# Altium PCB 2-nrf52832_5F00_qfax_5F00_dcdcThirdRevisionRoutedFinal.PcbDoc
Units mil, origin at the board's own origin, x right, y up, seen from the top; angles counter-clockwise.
Board outline 1524 x 818 mil, 2 copper layers (Top Layer, Bottom Layer), stack 62.8 mil thick; 31 components, 49 nets, 125 pads, 86 vias.
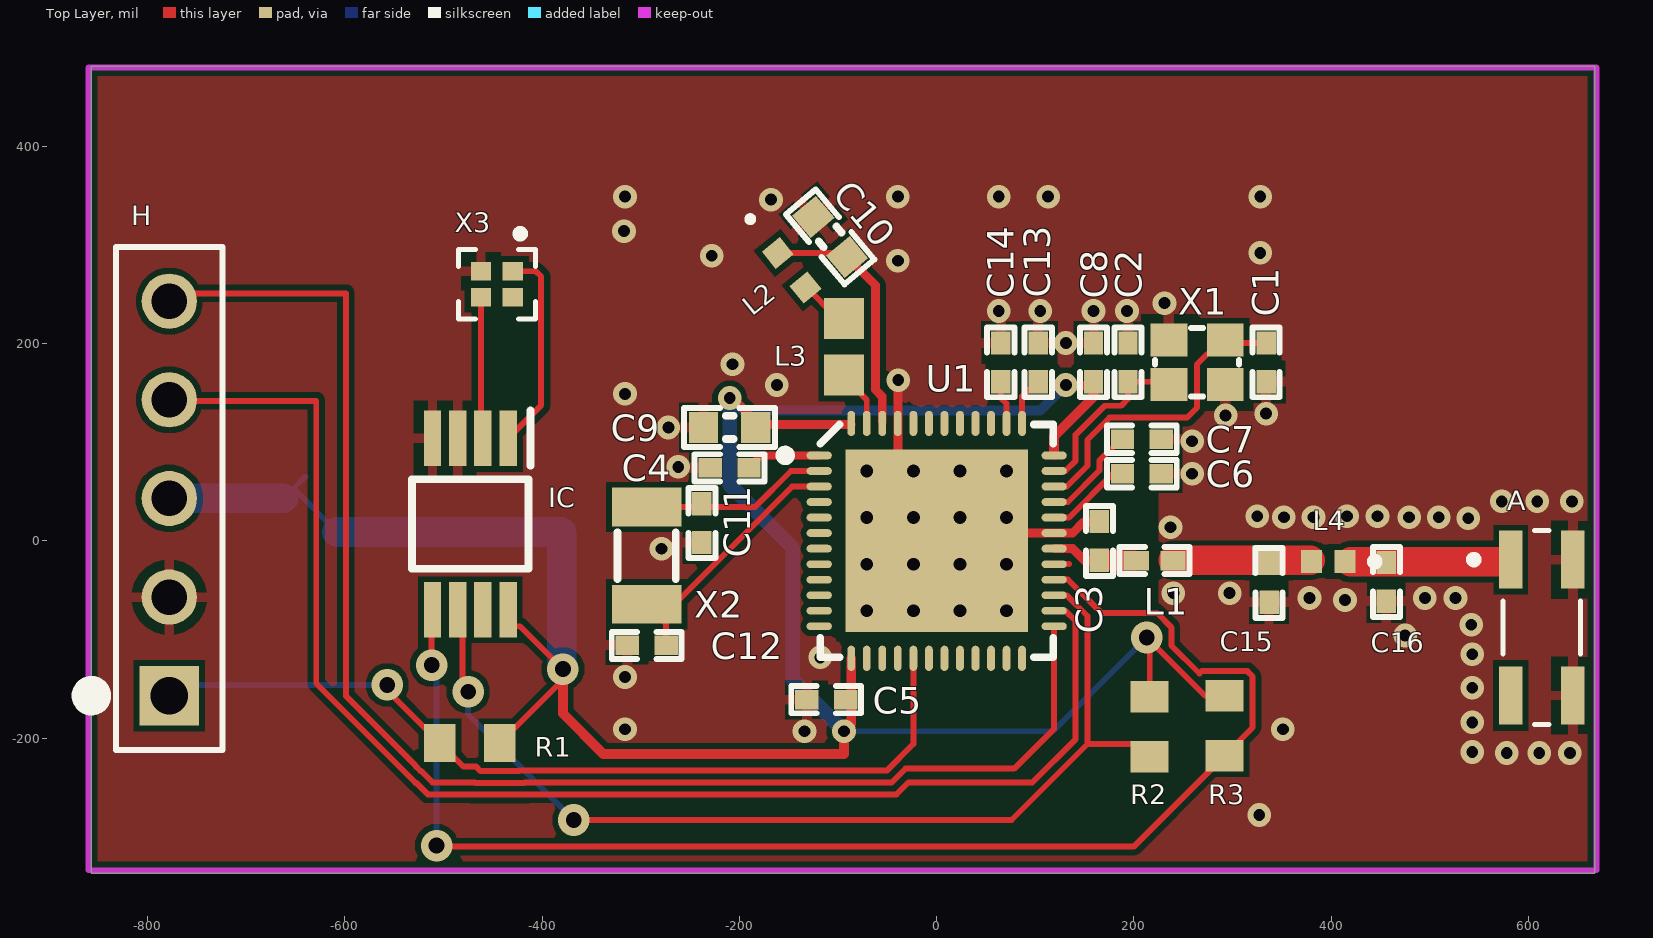
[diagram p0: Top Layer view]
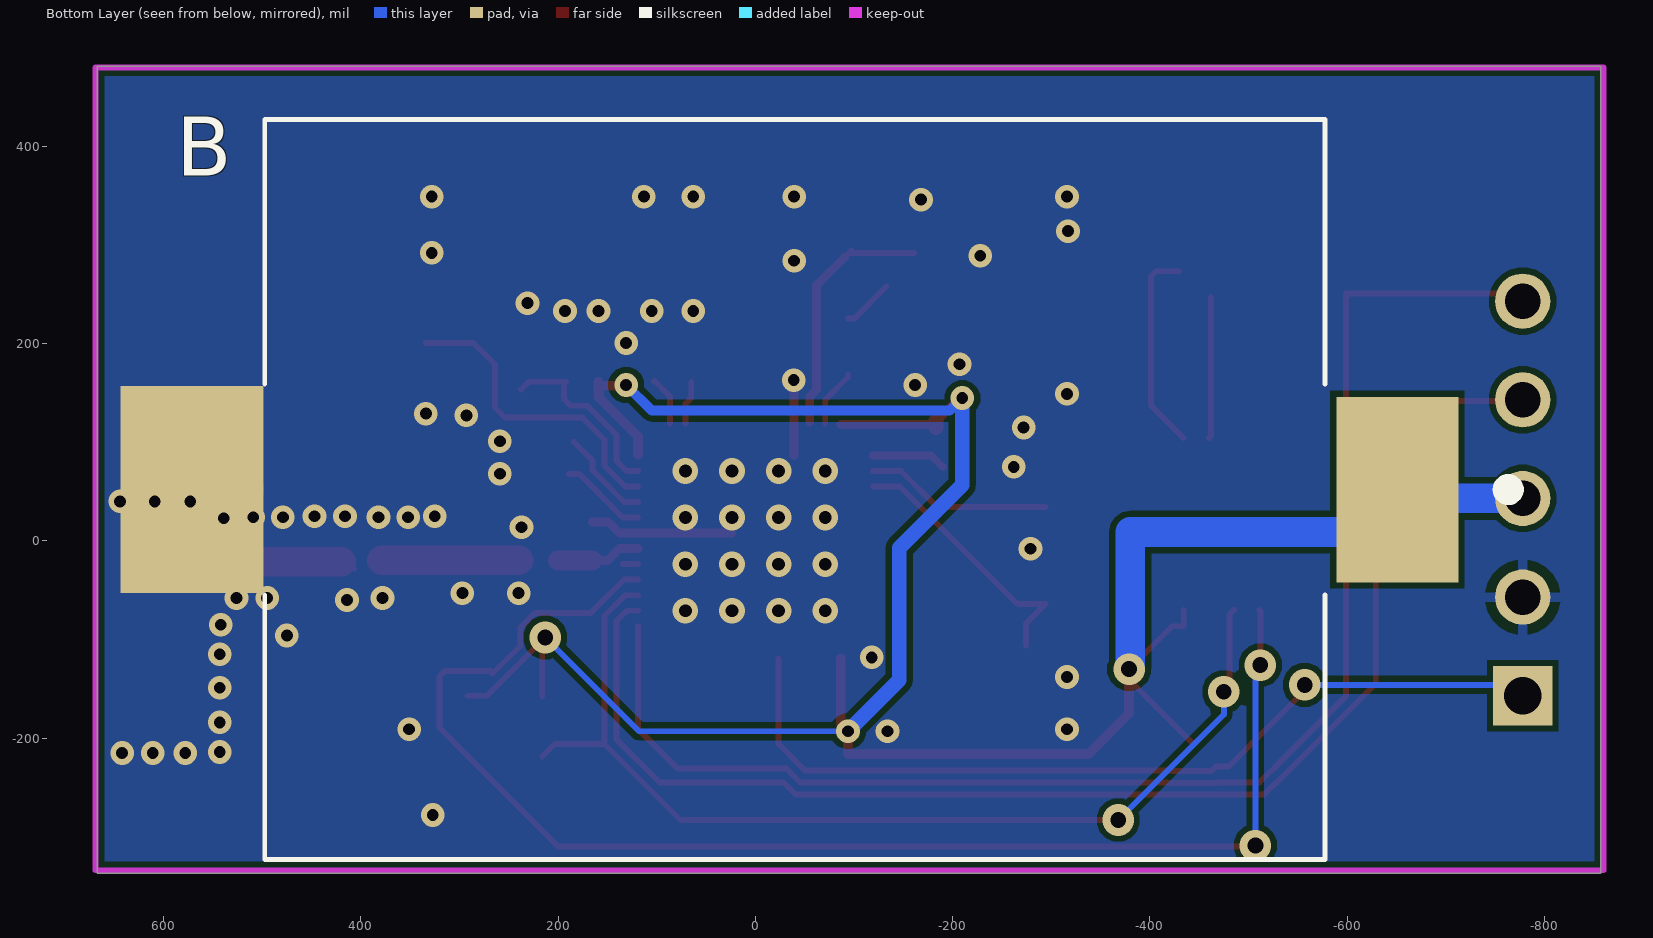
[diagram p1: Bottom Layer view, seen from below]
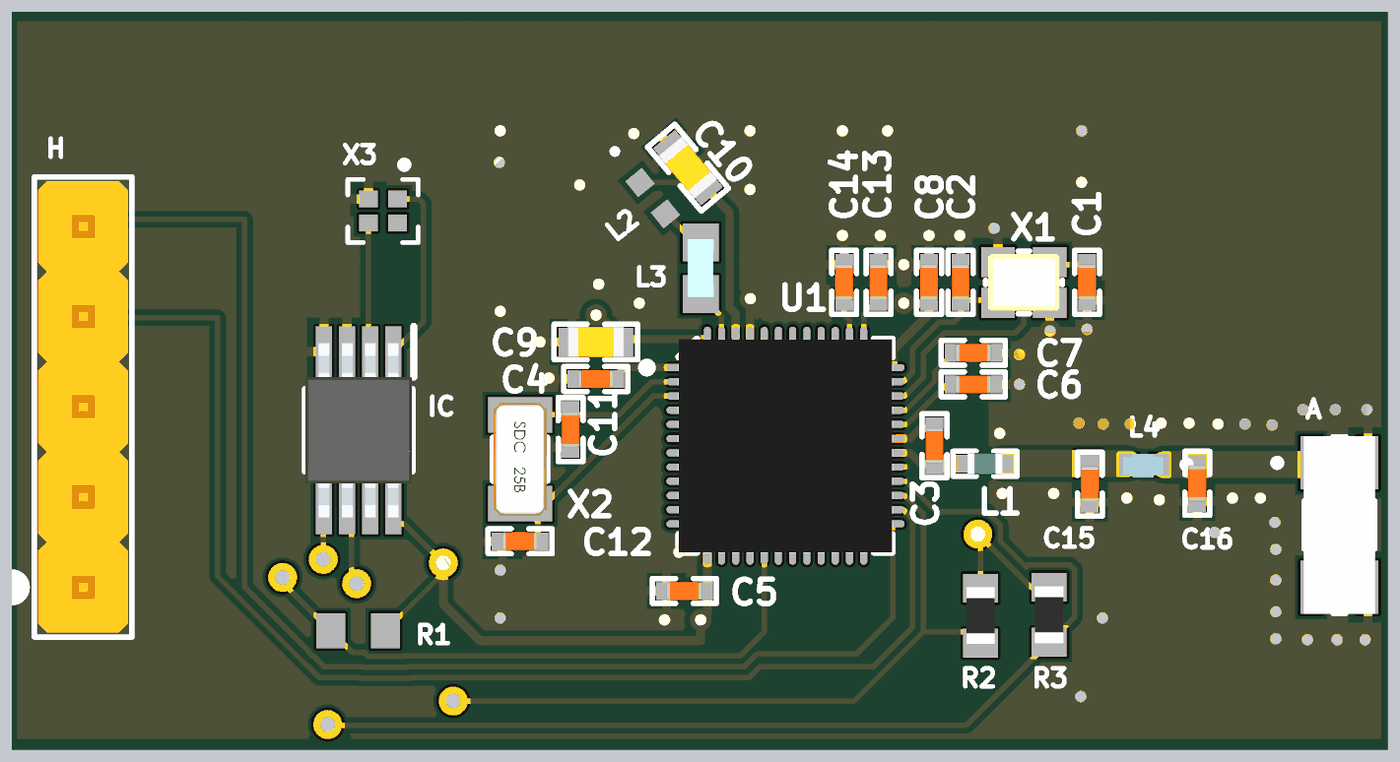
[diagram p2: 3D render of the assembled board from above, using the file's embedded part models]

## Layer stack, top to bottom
Top Solder: solder mask 0.4, Solder Resist, Dk 3.5
Top Layer: signal copper 1.4
Dielectric1: core 60, FR-4, Dk 4.8
Bottom Layer: signal copper 1.4
Bottom Solder: solder mask 0.4, Solder Resist, Dk 3.5

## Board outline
-857,-337 -857,481 667,481 667,-337

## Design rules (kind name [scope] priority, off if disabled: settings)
Clearance Polygon_ANT [(InNamedPolygon('Top_Layer-GND')) or (InNamedPolygon('Bottom_Layer-GND')) vs InNet('RF')] p1: gap=5 ignorepadtopadclearanceinfootprint=FALSE except(0: Arc-Hole Track-Hole SMDPad-Hole THPad-Hole Via-Hole Fill-Hole Poly-Hole Region-Hole Text-Hole)
Clearance Polygon [(InNamedPolygon('Top_Layer-GND')) or (InNamedPolygon('Bottom_Layer-GND'))] p2: gap=10 ignorepadtopadclearanceinfootprint=FALSE except(0: Arc-Hole Track-Hole SMDPad-Hole THPad-Hole Via-Hole Fill-Hole Poly-Hole Region-Hole Text-Hole)
Clearance [All] p3: gap=6 ignorepadtopadclearanceinfootprint=FALSE except(0: Arc-Hole Track-Hole SMDPad-Hole THPad-Hole Via-Hole Fill-Hole Poly-Hole Region-Hole Text-Hole)
ComponentClearance [All] p1 off: gap=10 collisioncheckmode=3 verticalgap=10 showdistances=FALSE
FabricationTestPointUsage TestPointUsage [All] p1: valid=0 allowmultiple=FALSE
FabricationTestpoint Testpoint [All] p1: side=3 testpointundercomponent=TRUE minsize=40 maxsize=100 preferedsize=60 minholesize=0 maxholesize=40 preferedholesize=32 testpointgrid=1 allowsidetop=TRUE allowsidebottom=TRUE usegrid=TRUE gridtolerance=0.01
Height [All] p1 off: minheight=0 maxheight=1000 prefheight=500
HoleSize [All] p1: absolutevalues=TRUE maxlimit=160 minlimit=12 maxpercent=80.000 minpercent=20.000
MinimumAnnularRing [All] p1 off: minimumring=6
PolygonConnect PolygonConnect_1 [isVia and innet(gnd)] p1: connectstyle=Direct reliefconductorwidth=10 reliefentries=4 polygonreliefangle="90 Angle" airgapwidth=10
PolygonConnect [All] p2: connectstyle=Relief reliefconductorwidth=10 reliefentries=4 polygonreliefangle="90 Angle" airgapwidth=10
RoutingVias [All] p1: holewidth=16 width=32 viastyle="Through Hole" minholewidth=10 minwidth=10 maxholewidth=28 maxwidth=50
SilkToSolderMaskClearance SilkscreenOverComponentPads [IsPad] p1: minsilkscreentomaskgap=10 clearancetoexposedcopper=TRUE
SolderMaskExpansion [All] p1: expansion=3 istentingtop=FALSE
Width [All] p1: maxlimit=110 minlimit=6 preferedwidth=6 minimp=50.000000 maximp=50.000000 favimp=50.000000
24 further rules are at their usual default settings.

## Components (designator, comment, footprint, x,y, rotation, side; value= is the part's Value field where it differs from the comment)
A "2.4 GHz Antenna" XDCR_2450AT42E010BE 613.5,-87.9 r90 top
B "Cr2032 Battery Holder" TE_796136-1 -39.98,52 r0 bottom
C1 "12pF" CAPC1005X04L 333.99,181.01 r270 top
C2 "12pF" CAPC1005X04L 193.99,181.01 r90 top
C3 "0.8pF" CAPC1005X04L 165,0 r270 top
C4 "100nF" CAPC1005X04L -210,74 r180 top
C5 "100nF" CAPC1005X04L -112,-161 r180 top
C6 "N.C." CAPC1005X04L 208,68 r180 top
C7 "100pF" CAPC1005X04L 208,103 r0 top
C8 "100nF" CAPC1005X04L 158.99,181.01 r90 top
C9 "4.7µF" CAPC1608X06L -210,115 r180 top
C10 "1.0µF" CAPC1608X06L -107.97,308.2 r310 top
C11 "12pF" CAPC1005X04L -238,18 r270 top
C12 "12pF" CAPC1005X04L -294,-106 r180 top
C13 "12pF" CAPC1005X04L 102.99,181.01 r90 top
C14 "12pF" CAPC1005X04L 64.99,181.01 r90 top
C15 "12pF" CAPC1005X04L 337,-42.69 r90 top
C16 "12pF" CAPC1005X04L 456,-41.69 r90 top
H "5 Pin Header" 22-28-4052 -778,-157 r270 top
IC "DS1339U-33+" SOP65P490X110-8N -472.8,17.09 r270 top
L1 "3.9nH" INDC1005X04L 221,-20 r0 top
L2 "0402 15nH L" IND_1005_TDK -147.07,274.37 r309 top
L3 "0603 10uH L" INDC1608X100N -94,196.66 r90 top
L4 "1.5nH Inductor" INDC1005X55N 397.01,-21 r0 top
R1 "4.7K R" RESC1508X55N -473.35,-205 r0 top
R2 "4.7K R" RESC1508X55N 216,-188.35 r90 top
R3 "4.7K R" RESC1508X55N 292,-187.35 r90 top
U1 "nRF52832-QFAA" QFN40P600X600X90-48N 0,0 r0 top locked
X1 "32MHz" BT-XTAL_2016 263.99,181.01 r180 top
X2 "32.768kHz" XTAL_3215 -294,-15 r270 top
X3 "32.7k oscillator 6pF" XTAL_ECS-.327-6-1210B-N-TR -445.86,260.19 r270 top

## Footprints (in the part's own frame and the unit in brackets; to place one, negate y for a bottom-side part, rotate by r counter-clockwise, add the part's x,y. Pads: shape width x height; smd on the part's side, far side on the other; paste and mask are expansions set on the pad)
22-28-4052 [mil]
  rect 60x60 hole 38 mask+0: 1(0,0)
  round 56 hole 36 mask+0: 2(-100,0) 3(-200,0) 4(-300,0) 5(-400,0)
  silkscreen extent -455,-89 55,54, body extent -450,-50 50,50, height 363
BT-XTAL_2016 [mm]
  rect 0.95x0.85 smd: 1(-0.725,-0.575) 2(0.725,-0.575) 3(0.725,0.575) 4(-0.725,0.575)
  silkscreen extent -1.08,-0.88 1.08,0.88, body extent -1,-0.8 1,0.8, height 0.51
CAPC1005X04L [mm]
  rect 0.6x0.5 smd: 1(-0.5,0) 2(0.5,0)
  silkscreen extent -0.9,-0.35 0.9,0.35, body extent -0.51,-0.25 0.51,0.25, height 0.5
CAPC1608X06L [mm]
  rect 0.75x0.8 smd: 1(-0.675,0) 2(0.675,0)
  silkscreen extent -1.17,-0.5 1.17,0.5, body extent -0.8,-0.43 0.8,0.43, height 0.8
IND_1005_TDK [mm]
  rect 0.576x0.6 smd paste+0 mask+0: 1(-0.568,0) 2(0.568,0)
  silkscreen extent -1.77,-0.08 -1.62,0.08, body extent 0,0 0.25,0.25, height 0.25
INDC1005X04L [mm]
  rect 0.65x0.5 smd: 1(-0.475,0) 2(0.475,0)
  silkscreen extent -0.9,-0.35 0.9,0.35, body extent -0.5,-0.3 0.5,0.3, height 0.5
INDC1005X55N [mm]
  rect 0.54x0.6 smd: 1(-0.432,0) 2(0.432,0)
  silkscreen extent 1.1,-0.1 1.3,0.1, body extent -0.58,-0.36 0.53,0.3, height 0.67
INDC1608X100N [mm]
  rect 1.06x1.02 smd: 1(-0.728,0) 2(0.728,0)
  body extent -0.81,-0.37 0.81,0.37, height 0.87
QFN40P600X600X90-48N [mm]
  oval 0.65x0.2 smd: 1(-3.025,2.2) 2(-3.025,1.8) 3(-3.025,1.4) 4(-3.025,1) 5(-3.025,0.6) 6(-3.025,0.2) 7(-3.025,-0.2) 8(-3.025,-0.6) 9(-3.025,-1) 10(-3.025,-1.4) 11(-3.025,-1.8) 12(-3.025,-2.2) 25(3.025,-2.2) 26(3.025,-1.8) 27(3.025,-1.4) 28(3.025,-1) 29(3.025,-0.6) 30(3.025,-0.2) 31(3.025,0.2) 32(3.025,0.6) 33(3.025,1) 34(3.025,1.4) 35(3.025,1.8) 36(3.025,2.2)
  oval 0.2x0.65 smd: 13(-2.2,-3.025) 14(-1.8,-3.025) 15(-1.4,-3.025) 16(-1,-3.025) 17(-0.6,-3.025) 18(-0.2,-3.025) 19(0.2,-3.025) 20(0.6,-3.025) 21(1,-3.025) 22(1.4,-3.025) 23(1.8,-3.025) 24(2.2,-3.025) 37(2.2,3.025) 38(1.8,3.025) 39(1.4,3.025) 40(1,3.025) 41(0.6,3.025) 42(0.2,3.025) 43(-0.2,3.025) 44(-0.6,3.025) 45(-1,3.025) 46(-1.4,3.025) 47(-1.8,3.025) 48(-2.2,3.025)
  rect 4.7x4.7 smd: 49(0,0)
  silkscreen extent -4.02,-3 3,3, body extent -3.02,-3.02 3.02,3.02, height 0.86
RESC1508X55N [mm]
  rect 0.81x0.98 smd: 1(-0.771,0) 2(0.771,0)
SOP65P490X110-8N [mm]
  rect 1.425x0.45 smd: 1(-2.212,0.975) 2(-2.212,0.325) 3(-2.212,-0.325) 4(-2.212,-0.975) 5(2.212,-0.975) 6(2.212,-0.325) 7(2.212,0.325) 8(2.212,0.975)
  silkscreen extent -2.93,-1.5 1.15,1.55, body extent -2.45,-1.5 2.45,1.5, height 1.1
TE_796136-1 [mm]
  rect 3.15x4.78 smd: 1(-15.52,0)
  rect 3.683x5.339 smd mask+0.076: 2(15.52,0)
  silkscreen extent -18.57,-9.53 13.65,9.53, body extent -15.87,-10.13 16.13,9.87, height 5.31
XDCR_2450AT42E010BE [mm]
  rect 1.5x0.6 smd: 1(1.75,0.8) 2(-1.75,0.8) 3(-1.75,-0.8) 4(1.75,-0.8)
  silkscreen extent -2.5,-1 2.5,1.85, body extent -2.5,-1 2.5,1, height 1.31
XTAL_3215 [mm]
  rect 1x1.8 smd: 1(-1.25,0) 2(1.25,0)
  silkscreen extent -0.6,-0.75 0.6,0.75, body extent -1.6,-0.75 1.6,0.75, height 0.81
XTAL_ECS-.327-6-1210B-N-TR [mm]
  rect 0.47x0.52 smd: 1(-0.335,0.41) 2(-0.335,-0.41) 3(0.335,-0.41) 4(0.335,0.41)
  silkscreen extent -1.4,-0.99 0.89,0.99

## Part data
A: library part 2450AT42E010BE, "JOHANSON TECHNOLOGY - 2450AT42E010BE - Chip-Antenne, Einzelband, 2.4GHz, 50 Ohm, 5mm x 2mm x 1.5mm", Manufacturer=Johanson, Max Power Dissipation=2W, Package="FBGA-780 Johanson", Supplier Part Number 1=712-1624-1-ND
B: library part 796136-1, "Surface Mount Battery Holder For 1; Leaf Spring Contact", Manufacturer="TE Connectivity", Package=None, Supplier Part Number 1=A99327CT-ND
C1 C2 C11 C12 C13 C14: library part C0402-12p, "Capacitor, NP0, ±2%"
C3: library part C0402-0.8p, "Capacitor, NP0, ±5%"
C4 C5 C8: library part C0402-100n, "Capacitor, X7R, ±10%"
C6: library part C0402-N.C., "Not mounted"
C7: library part C0402-100p, "Capacitor, NP0, ±5%"
C9: library part C0603-4µ7, "Capacitor, X5R, ±10%"
C10: library part C0603-1µ0, "Capacitor, X7R, ±10%"
C15 C16: "CAP CER 12PF 50V C0G/NPO 0402", Case Code (Imperial)=0402, Case Code (Metric)=1005, Dielectric=C0G, Max Operating Temperature=125°C, Min Operating Temperature=-55°C, Package Quantity=1, Part Number=C0402-12p, Resistor Type=Ceramic, Supplier Part Number 1=311-1016-1-ND, Tolerance=5%, Voltage Rating=50V
H: library part 22-28-4052, "CONN HEADER 5POS .100 VERT TIN", Color=Black, Contact Resistance=20mR, Current Rating=4A, Flammability Rating="UL94 V-0", Manufacturer=Molex, Max Operating Temperature=75°C, Max Voltage Rating (DC)=250.25kV, Min Operating Temperature=0°C, Package Quantity=1, Supplier Part Number 1=22-28-4052-ND, Voltage Rating=250V
IC: "Real Time Clock Serial 8-Pin uMAX T/R", Case/Package=UMAX, Manufacturer=Maxim, Manufacturer Part Number=DS1339U-33+T&R, Manufacturer_Name="Maxim Integrated", Max Operating Temperature=85°C, Max Supply Voltage=5.5V, Min Operating Temperature=-40°C, Min Supply Voltage=2.97V, Operating Supply Voltage=3.3V, Package Quantity=1, Supplier Part Number 1=DS1339U-33+T&RCT-ND
L1: library part L0402-3n9, "High frequency chip inductor ±5%", Manufacturer=Murata, Manufacturer Part Number=LQP15MN3N9B02D, Supplier part number=490-1131-1-ND
L2: library part MLK1005S15NJT000, "Ind RF Chip Unshielded Multi-Layer 15nH 5% 100MHz 7Q-Factor 300mA 0402 Punched Paper T/R", Case Code (Imperial)=0402, Case Code (Metric)=1005, Current Rating=300mA, DC Resistance (DCR)=500mR, Inductance=15nH, Manufacturer="TDK EPCOS", Max Operating Temperature=125°C, Min Operating Temperature=-55°C, Package Quantity=1, Self Resonant Frequency=4GHz, Supplier Part Number 1=445-1469-1-ND, Test Frequency=100MHz, Tolerance=5%
L3: library part CBMF1608T100K, "Ind Power Chip Wirewound 10uH 10% 2.52MHz Ferrite 380mA 0603 T/R", Case Code (Imperial)=0603, Case Code (Metric)=1608, Current Rating=380mA, DC Resistance (DCR)=468mR, Inductance=10uH, Inductance Tolerance=10%, Manufacturer="Taiyo Yuden", Max Operating Temperature=105°C, Min Operating Temperature=-40°C, Package="1608 Taiyo Yuden", Package Quantity=3000, Resistor Type=Wirewound, Saturation Current=115mA, Self Resonant Frequency=32MHz, Supplier Part Number 1=587-1720-1-ND, Test Frequency=2.52MHz
L4: library part LQG15HS1N5S02D, "Fixed Inductors 1.5nH +/-0.3 Hi-Freq", Case Code (Imperial)=0402, Case Code (Metric)=1005, Current Rating=300mA, DC Resistance (DCR)=100mR, Inductance=1.5nH, Manufacturer=Murata, Max Operating Temperature=125°C, Min Operating Temperature=-55°C, Package="1005 Murata", Package Quantity=10000, Self Resonant Frequency=6GHz, Supplier Part Number 1=490-2612-1-ND, Test Frequency=100MHz
R1 R2 R3: library part MCT0603MD4701DP500, "RES SMD 4.7K OHM 0.5% 0.15W 0603", Case Code (Imperial)=0603, Case Code (Metric)=1608, Manufacturer=Vishay, Max Operating Temperature=175°C, Max Power Dissipation=150mW, Min Operating Temperature=-55°C, Package=None, Package Quantity=1, Power Rating=125mW, Resistance=4.7kR, Resistance Tolerance=0.5%, Resistor Type="Thin Film", Supplier Part Number 1=MCT0603-4.7K-MDCT-ND, Temperature Coefficient=25ppm/°C, Voltage Rating=75V
U1: "Multi-protocol Bluetooth Low Energy, ANT and 2.4GHz proprietary system-on-chip", Manufacturer="Nordic Semiconductor"
X1: library part XTAL_SMD2016_32MHz_8pF_General, "XTAL SMD 2016, 32MHz, Cl=8pF, Total Tol: ±40ppm"
X2: library part XTAL_SMD3215_32.768kHz_9pF_General, "XTAL SMD 3215, 32.768kHz, Cl=9pF, Total Tol: ±50ppm"
X3: library part ECS-.327-6-1210B-N-TR, "Crystal 32.768kHz 6pF 4-Pin SMD T/R", Manufacturer="ECS International", Package=None, Supplier Part Number 1=50-ECS-.327-6-1210B-N-TR-ND

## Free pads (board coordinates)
  rect 30x30 smd: 0(335,-19.75)

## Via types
v1: diameter 24, hole 12, Top Layer to Bottom Layer, tented both sides, 63 vias
v2: diameter 25.98, hole 12.99, Top Layer to Bottom Layer, 16 vias
v3: diameter 32, hole 16, Top Layer to Bottom Layer, 7 vias

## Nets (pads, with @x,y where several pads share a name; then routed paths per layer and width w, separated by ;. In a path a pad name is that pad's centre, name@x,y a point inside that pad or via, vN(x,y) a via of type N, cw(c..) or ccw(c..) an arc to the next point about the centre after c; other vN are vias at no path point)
DEC1: C4.1 U1.1 | length 76
  Top Layer w8: C4.1@-190.16,74.76 -178.31,86.61 U1.1
DEC2: C6.2 U1.32 | length 88.3
  Top Layer w6: U1.32 134.3,23.62 178.67,68 C6.2@189,68
DEC3: C7.1 U1.33 | length 96
  Top Layer w6: U1.33 133.07,39.37 165,71.3 165,81.19 C7.1@184.06,100.25
DEC4: C10.2 L2.1 U1.46 | length 263.5
  Top Layer w6: L2.1 -94.79,291.75 C10.2 C10.2@-97.42,294.37
  Top Layer w9: C10.2 -62,258.95 -62,153.2 -55.12,146.32 U1.46@-55.12,120.3
GND: A.3 A.4 B.2 C1.2 C2.2 C3.1 C4.2 C5.2 C6.1 C7.2 C8.2 C9.2 C10.1 C11.2 C12.2 C13.2 C14.2 C15.1 C16.1 H.2 IC.3 IC.4 U1.31 U1.45 U1.49 X1.2 X1.4 X3.2 | length 222.1
  Top Layer w9: U1.49@-39.37,86.61 U1.45 v1@-39.37,163 ; U1.49@24.31,8 137.77,8 149.06,19.3 C3.1@165.31,19.3
  other v1: 327,-278 578,-215 611,-215 642,-215 543,-214 -134,-193 -316,-191 351,-191 543,-184 543,-149 -316,-138 -118,-118.11 543,-115 475,-96 542,-85 414,-60 378,-58 495,-58 526,-58 240,-53 297,-53 -279,-8 237.16,13.76 539,23 352,24 382,24 479,24 509,24 325,25 416,25 447,25 573,40 609,40 644,40 259,68 -262,75 259,101 -272,115 293,127.2 334,129 -316,149 -162,158 -39,163 -207,179 130.99,200.69 63,233 105,233 159,233 193,233 230.99,241.01 -39.37,284 -228,289 328,292 -317,314 -168,346 -316,349 -39.37,349 63,349 113,349 328,349
  other v2: -70.87,-70.87 -23.62,-70.87 23.62,-70.87 70.87,-70.87 -70.87,-23.62 -23.62,-23.62 23.62,-23.62 70.87,-23.62 -70.87,23.62 -23.62,23.62 23.62,23.62 70.87,23.62 -70.87,70.87 -23.62,70.87 23.62,70.87 70.87,70.87
NetA_1: A.1 C16.2 L4.2 | length 168.6
  Top Layer w6: L4.2@407,-28.02 L4.2 ; C16.2@455,-21 C16.2 C16.2@457,-21 ; A.1@580,-21 A.1
  Top Layer w30: L4.2@420.02,-21 C16.2@455,-21 ; C16.2@457,-21 A.1@575,-21
NetC3_2: C3.2 L1.1 U1.30 | length 86.6
  Top Layer w9: U1.30 137.79,-7.87 149.99,-20.07 C3.2@165.32,-20.07
  Top Layer w20: C3.2@165,-19.87 L1.1@200.31,-19.87
NetIC_1: IC.1 X3.1 | length 208.6
  Top Layer w6: IC.1 -401,137.58 -401,268 -406.38,273.38 X3.1
NetIC_2: IC.2 X3.3 | length 143.7
  Top Layer w6: X3.3 -462,106.17 IC.2
NetL2_2: L2.2 L3.2 | length 52.5
  Top Layer w6: L2.2@-133,258 -100.32,225.32 L3.2
NetL3_1: L3.1 U1.47 | length 58.5
  Top Layer w6: L3.1 -94,166.11 -70.87,142.98 U1.47
P0.00/XL1: C11.1 U1.2 X2.1 | length 190.1
  Top Layer w6: X2.1 -184.36,34.21 -147.71,70.87 U1.2
P0.01/XL2: C12.1 U1.3 X2.2 | length 274.3
  Top Layer w6: C12.1 -274.32,-83.9 X2.2 -265.82,-64.21 -146.49,55.12 U1.3
P0.02/AIN0: U1.4
P0.03/AIN1: U1.5
P0.04/AIN2: U1.6
P0.05/AIN3: U1.7
P0.06: U1.8
P0.07: U1.9
P0.08: U1.10
P0.09: U1.11
P0.10: U1.12
P0.11: U1.14
P0.12: U1.15
P0.13: U1.16
P0.14: H.1 R1.1 U1.17 | length 896.6
  Top Layer w6: v3(-557,-146) -557,-151.71 R1.1 -479.73,-228.98 -466.98,-228.98 -462.67,-233.29 -423.33,-233.29 -423.04,-233 -50.62,-233 -23.62,-206 U1.17
  Bottom Layer w6: H.1 -767,-146 v3(-557,-146)
P0.15: U1.18
P0.16: U1.19
P0.17: U1.20
P0.18: U1.21
P0.19: U1.22
P0.20: U1.23
P0.21: U1.24
P0.22: IC.6 R2.1 U1.27 | length 1060.2
  Top Layer w6: IC.6 -480.63,-74.96 -480.63,-147.37 v3(-475,-153) ; v3(-368,-283) 75.89,-283 152.89,-206 ; U1.27 131.85,-55.12 152.89,-76.16 152.89,-206 ; R2.1 203.29,-206 152.89,-206
  Bottom Layer w6: v3@-480,-153 v3(-475,-153) -475,-176 v3(-368,-283)
P0.23: IC.5 R3.1 U1.28 | length 1426.3
  Top Layer w6: v3(-512,-126) -512,-70.82 IC.5 ; v3(-507,-309) -507,-310 199.71,-310 R3.1 320.29,-189.42 320.29,-137.33 315.02,-132.06 268.98,-132.06 266.5,-134.53 238,-106.03 238,-87.64 223.36,-73 166.7,-73 133.07,-39.37 U1.28
  Bottom Layer w6: v3(-512,-126) -507,-131 v3(-507,-309)
P0.24: U1.29 | length 15.2
  Top Layer w6: U1.29 134.3,-23.62
P0.25: C13.1 U1.37 | length 50.7
  Top Layer w6: U1.37 86.61,146.63 102.15,162.16 C13.1
P0.26: C14.1 U1.38 | length 44.7
  Top Layer w6: C14.1 64.99,145.01 70.87,139.13 U1.38
P0.27: U1.39
P0.28/AIN4: U1.40
P0.29/AIN5: U1.41
P0.30/AIN6: U1.42
P0.31/AIN7: U1.43
RF: C15.2 L1.2 L4.1 pad.0 | length 141.1
  Top Layer w6: C15.2@337,-24 338,-23 C15.2
  Top Layer w30: L1.2@240.02,-19.75 pad.0 L4.1@378.75,-19.75
SWDCLK: H.5 U1.25 | length 1471.9
  Top Layer w6: H.5 -770,251 -599,251 -599,-157 -528.65,-227.35 -528.65,-228.02 -523.38,-233.29 -522.71,-233.29 -511,-245 -467.93,-245 -467.64,-245.29 -418.36,-245.29 -418.07,-245 -45.65,-245 -31.65,-231 78.58,-231 119.09,-190.49 U1.25
SWDIO: H.4 U1.26 | length 1421.8
  Top Layer w6: H.4 -777,142 -629,142 -629,-144.64 -528.35,-245.29 -527.68,-245.29 -515.97,-257 -472.91,-257 -472.61,-257.29 -413.39,-257.29 -413.09,-257 -40.68,-257 -28.68,-245 96.92,-245 140.89,-201.03 140.89,-81.26 130.5,-70.87 U1.26
VDD_NRF: B.1 C5.1 C8.1 C9.1 H.3 IC.8 R1.2 R2.2 R3.2 U1.13 U1.36 U1.48 | length 2753.6
  Top Layer w6: R1.2 -379,-141 v3(-379,-130) -422.41,-86.59 -434.41,-86.59 IC.8 ; v3(213,-98) v3@216,-101 ; R2.2 v3@216,-101 ; R3.2 272,-157 v3@216,-101
  Top Layer w9: v1(-209.84,144.76) -206.58,144.76 -183.27,121.46 -179.92,118.11 U1.48@-87,118.11 ; v1(-94,-193) v1@-86.61,-185.61
  Top Layer w10: v3@-379,-141 -379,-175 -338,-216 -94,-216 v1(-94,-193) ; v1@-86.61,-185.61 U1.13 ; U1.36@119,87.69 119,105.83 158.99,145.83 C8.1 ; v1(130.99,158.01) 131.68,157.32 C8.1@158.99,157.32
  Top Layer w15: C9.1@-183.27,114.76 C9.1@-183.27,121.46
  Bottom Layer w6: B.1@-662.05,43 B.1@-652.02,53.02 ; B.1 B.1@-608,9 ; v3(-379,-130) v3@-373,-124 ; v1(-94,-193) 118,-193 v3(213,-98) ; B.1@-652.02,53.02 B.1@-640.05,65 ; B.1@-652.02,53.02 B.1@-640.05,65 ; B.1@-652.02,53.02 B.1@-640.05,65
  Bottom Layer w10: v1(-209.84,144.76) -197.08,132 104.99,132 v1(130.99,158.01)
  Bottom Layer w15: v1(-209.84,144.76) -209.84,56.66 -145.95,-7.24 -145.95,-141.05 v1(-94,-193)
  Bottom Layer w30: H.3 B.1@-662.05,43 ; B.1@-608,9 -380,9 -380,-129 v3(-379,-130)
XC1: C1.1 U1.34 X1.1 | length 316.4
  Top Layer w6: U1.34 131.85,55.12 152.89,76.16 152.89,102.47 175.42,125 253.99,125 263.99,135.01 263.99,179.01 285.68,200.69 C1.1
XC2: C2.1 U1.35 X1.3 | length 186.4
  Top Layer w6: U1.35 130.5,70.87 140.89,81.26 140.89,107.58 170.31,137 187,137 193.99,143.99 C2.1@193.99,161.01 ; C2.1@191.99,161.32 229.65,161.32 X1.3@237.53,153.45
pads on no net: A.2 IC.7 U1.44 X3.4

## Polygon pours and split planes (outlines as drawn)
GND on Bottom Layer "TopGndPolygon" (solid, remove dead copper, pour order 1008): -857,479 666,479 664,477 664,-328 -853,-328 -855,-330
GND on Bottom Layer "Bottom_Layer-GND" (solid, remove dead copper, pour order 1006): -400,400 -400,-250 400,-250 400,401
GND on Top Layer "TopGndPolygon" (solid, remove dead copper, pour order 1007): -856,478 -855,479 667,479 667,-331 669,-333 667,-335 -856,-335
GND on Top Layer "Top_Layer-GND" (solid, remove dead copper, pour order 1004): -400,400 -400,-250 400,-250 400,400

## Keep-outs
Keep-Out Layer:
  lines w6: -860,-334 -860,480 669,480 669,-334 -860,-334

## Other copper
Top Layer:
  pour cut-out: 225,-63 117,-63 117,51 225,51

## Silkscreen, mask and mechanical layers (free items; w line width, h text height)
Mechanical 1:
  lines w6: -341,-218 -341,377 359,377 359,-218 -341,-218

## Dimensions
669,480 to 669,-334 on Mechanical 3
-860,-334 to 669,-334 on Mechanical 3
